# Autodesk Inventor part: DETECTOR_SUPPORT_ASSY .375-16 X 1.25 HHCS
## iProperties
Shininess: 64.0
Length Units: 11272
Angle Units: 11279
Time Units: 11290
Mass Units: 11286
Length Display Precision: 3
Angle Display Precision: 2
Compacted: True
Part Number: DETECTOR_SUPPORT_ASSY .375-16 X 1.25 HHCS
Document SubType Name: Modeling
Created: 2004-08
Designer: John Blackburn
Material: STAINLESS_STEEL, AUSTENITIC
Manufacturer: Standard
Standards Organization: Custom
Density: 0.0
Volumn: 0.0
Area: 0.0
PropertySet Name: Model Information
Control State: 0
Master: False
Checked Out: False
Author: John Blackburn
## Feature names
1. Base1
